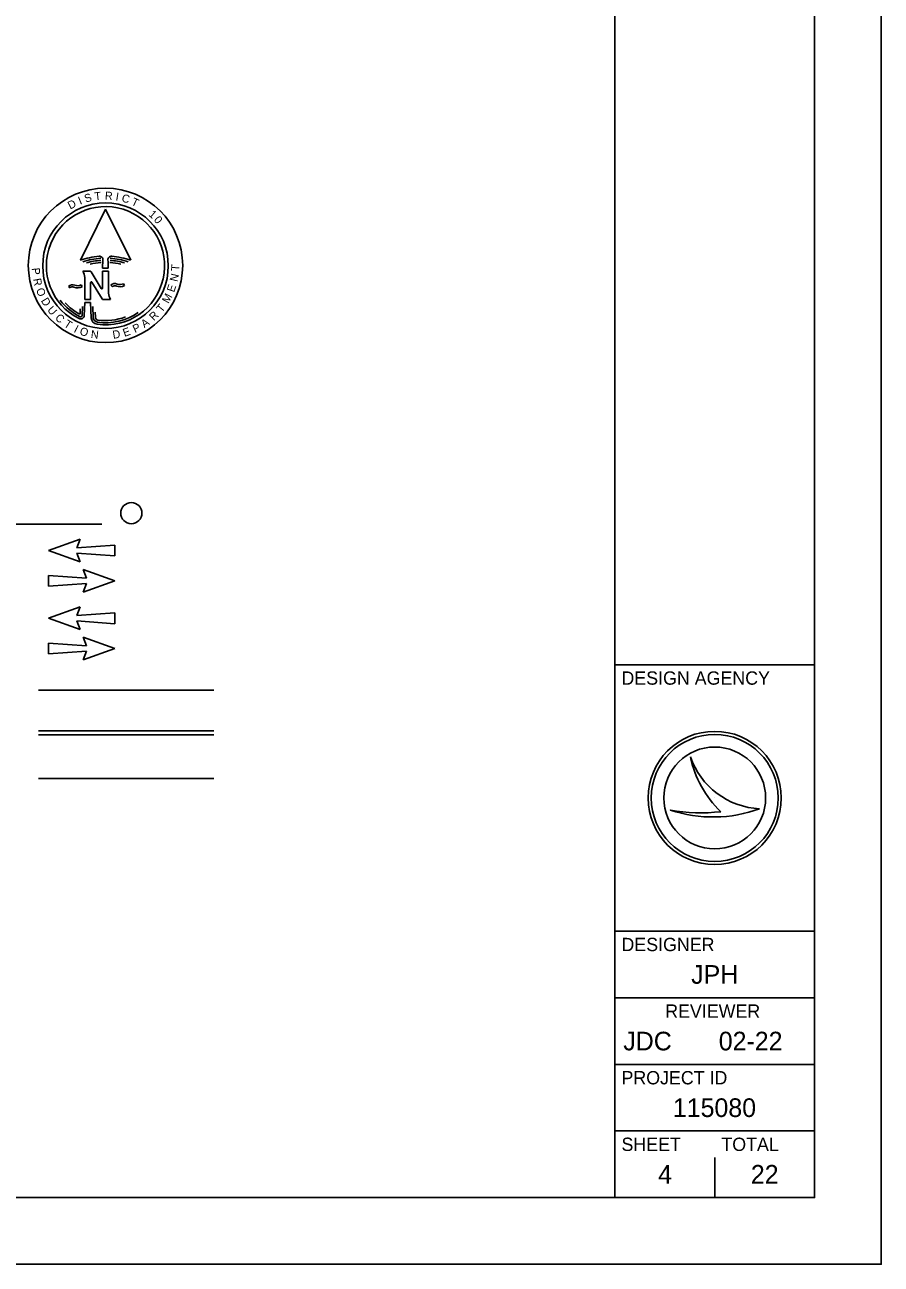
# Model space of a CAD drawing. Extents: x 0 to 34, y 0 to 22.
# Drawn here: x 27.57 to 34, y 0 to 9.3 of the extents above; entities that cross this region are included whole.
import ezdxf

# ---------------------------------------------------------------- set-up
doc = ezdxf.new("R2010")
doc.units = 0
for name, color, linetype in [('Default', 7, 'Continuous'), ('SH_Border', 7, 'Continuous'), ('SH_Cut_Line', 7, 'Continuous'), ('SH_Data', 7, 'Continuous'), ('TX_P_1', 7, 'Continuous')]:
    doc.layers.add(name, color=color, linetype=linetype)

msp = doc.modelspace()

# ---------------------------------------------------------------- linework, layer by layer
at = {"layer": 'Default'}
for p, q in [((27.9872, 7.5356), (28.1762, 7.9196)), ((28.1762, 7.9196), (28.3652, 7.5356)), ((28.1548, 7.4768), (28.1572, 7.5385)), ((28.0049, 7.4554), (28.0587, 7.4554)), ((28.0679, 7.4504), (28.1441, 7.3246)), ((28.1541, 7.3273), (28.1541, 7.4554)), ((28.1541, 7.4554), (28.1978, 7.4554)), ((28.1969, 7.4768), (28.1548, 7.4768)), ((28.1761, 7.4949), (28.1761, 7.4949)), ((28.1761, 7.4949), (28.1761, 7.4949)), ((28.1762, 7.4949), (28.1762, 7.4949)), ((28.1762, 7.4949), (28.1762, 7.4949)), ((28.1762, 7.4949), (28.1762, 7.4949)), ((28.1762, 7.4949), (28.1762, 7.4949)), ((28.1978, 7.4554), (28.1978, 7.2896)), ((28.0012, 7.3379), (27.9935, 7.3518)), ((28.0209, 7.2414), (28.0209, 7.4072)), ((28.0647, 7.3695), (28.0647, 7.2414)), ((28.1509, 7.2466), (28.0747, 7.3723)), ((28.3196, 7.3465), (28.3119, 7.3603)), ((27.8982, 7.3394), (27.9098, 7.3284)), ((28.2166, 7.3481), (28.2283, 7.3371)), ((27.9867, 7.1716), (27.9847, 7.1303)), ((28.0034, 7.1895), (28.0003, 7.1214)), ((28.0209, 7.22), (28.0162, 7.1202)), ((28.0647, 7.2414), (28.0209, 7.2414)), ((28.0647, 7.22), (28.0209, 7.22)), ((28.068, 7.1049), (28.0647, 7.22)), ((28.0817, 7.1887), (28.084, 7.1073)), ((28.2139, 7.2414), (28.16, 7.2414)), ((28.099, 7.1453), (28.1, 7.1078)), ((28.1475, 5.5549), (23.1299, 5.5549)), ((27.748, 5.3577), (27.9859, 5.4429)), ((27.9859, 5.4429), (27.9606, 5.3781)), ((27.9606, 5.3781), (28.2465, 5.3983)), ((28.2465, 5.3983), (28.2465, 5.3167)), ((27.9859, 5.2722), (27.748, 5.3577)), ((28.2465, 5.3167), (27.9607, 5.3371)), ((27.9607, 5.3371), (27.9859, 5.2722)), ((28.0339, 5.1506), (28.0085, 5.2154)), ((28.0085, 5.2154), (28.2467, 5.13)), ((27.7481, 5.0894), (27.7479, 5.1706)), ((27.7479, 5.1706), (28.0339, 5.1506)), ((28.2467, 5.13), (28.0088, 5.0448)), ((28.0339, 5.1094), (27.7481, 5.0894)), ((28.0088, 5.0448), (28.0339, 5.1094)), ((27.748, 4.849), (27.9859, 4.9342)), ((27.9859, 4.9342), (27.9606, 4.8694)), ((27.9859, 4.7635), (27.748, 4.849)), ((27.9606, 4.8694), (28.2465, 4.8896)), ((28.2465, 4.8896), (28.2465, 4.808)), ((28.2465, 4.808), (27.9607, 4.8285)), ((27.9607, 4.8285), (27.9859, 4.7635)), ((27.7481, 4.5807), (27.7479, 4.6619)), ((27.7479, 4.6619), (28.0339, 4.6419)), ((28.0339, 4.6419), (28.0085, 4.7067)), ((28.0085, 4.7067), (28.2467, 4.6213)), ((28.0339, 4.6008), (27.7481, 4.5807)), ((28.2467, 4.6213), (28.0088, 4.5361)), ((28.0088, 4.5361), (28.0339, 4.6008)), ((28.9905, 4.3084), (27.6732, 4.3084)), ((28.9905, 4.0047), (27.6732, 4.0047)), ((28.9905, 3.9748), (27.6732, 3.9748)), ((28.9905, 3.6461), (27.6732, 3.6461))]:
    msp.add_line(p, q, dxfattribs=at)
for centre, radius in [((28.1761, 7.4975), 0.5795), ((28.1761, 7.4948), 0.4715)]:
    msp.add_circle(centre, radius, dxfattribs=at)
for centre, radius, start, end in [((28.1761, 7.4948), 0.4438, 261.93684, 243.42086), ((28.1761, 7.0035), 0.5647, 94.8642, 109.5471), ((28.1761, 7.0035), 0.5486, 93.73826, 108.099), ((28.1305, 7.5395), 0.0267, 357.77965, 94.8642), ((28.2212, 7.5395), 0.0267, 85.19546, 182.12377), ((40.4649, 7.9936), 12.2788, 182.12377, 182.41208), ((28.1761, 7.0035), 0.5486, 71.901, 86.26141), ((28.1761, 7.0035), 0.5647, 70.45266, 85.19546), ((27.8939, 7.3917), 0.128, 7.00127, 29.86863), ((28.1761, 7.0035), 0.5326, 93.73826, 105.49674), ((28.0587, 7.4447), 0.0107, 31.24731, 90), ((28.1761, 7.0035), 0.5165, 93.73826, 102.75761), ((28.1761, 7.0035), 0.5165, 77.24239, 86.26141), ((28.1761, 7.0035), 0.5326, 74.50326, 86.26141), ((27.9288, 7.3106), 0.0421, 65.79325, 136.76575), ((27.9669, 7.3987), 0.0539, 247.19582, 299.48448), ((28.0701, 7.3695), 0.00535, 31.24622, 180), ((28.2472, 7.3193), 0.0421, 65.79325, 136.76575), ((28.2854, 7.4073), 0.0539, 247.19582, 299.48448), ((27.9288, 7.3106), 0.026, 65.79325, 136.76575), ((27.9667, 7.3988), 0.07, 247.19582, 299.48448), ((28.1487, 7.3274), 0.00535, 211.24622, 0), ((28.3249, 7.3052), 0.128, 187.00127, 209.86863), ((28.2472, 7.3193), 0.026, 65.79325, 136.76575), ((28.2852, 7.4074), 0.07, 247.19582, 299.48448), ((28.1761, 7.4948), 0.4277, 217.27521, 243.42077), ((28.1761, 7.4948), 0.4117, 222.56637, 242.2942), ((28.16, 7.2521), 0.0107, 211.24731, 270), ((27.9896, 7.1219), 0.0267, 243.42086, 356.26509), ((27.9896, 7.1219), 0.0107, 243.42077, 357.31292), ((28.1214, 7.1084), 0.0535, 183.80636, 261.93684), ((28.1214, 7.1084), 0.0374, 181.63859, 261.94105), ((28.1214, 7.1084), 0.0214, 181.63732, 261.93938), ((28.1761, 7.4948), 0.4277, 261.94105, 304.81679), ((28.1761, 7.4948), 0.4117, 261.93938, 291.31687)]:
    msp.add_arc(centre, radius, start, end, dxfattribs=at)
at = {"layer": 'SH_Border'}
for p, q in [((32, 0.5), (32, 21.5)), ((32, 4.5), (33.5, 4.5)), ((32, 2.5), (33.5, 2.5)), ((32, 2), (33.5, 2)), ((32, 1.5), (33.5, 1.5)), ((32, 1), (33.5, 1))]:
    msp.add_line(p, q, dxfattribs=at)
msp.add_lwpolyline([(1.5, 21.5), (33.5, 21.5), (33.5, 0.5), (1.5, 0.5)], close=True, dxfattribs=at)
at = {"layer": 'SH_Cut_Line'}
msp.add_lwpolyline([(0, 0), (34, 0), (34, 22), (0, 22)], close=True, dxfattribs=at)
at = {"layer": 'SH_Data'}
for p, q in [((32.5674, 3.8096), (32.5675, 3.8096)), ((32.75, 3.5), (32.75, 3.5)), ((32.4172, 3.4095), (32.4172, 3.4095)), ((33.0873, 3.4185), (33.0873, 3.4185)), ((32.75, 0.5), (32.75, 0.8)), ((32.375, 0.675), (32.375, 0.675))]:
    msp.add_line(p, q, dxfattribs=at)
for radius in [0.5, 0.4768, 0.4768, 0.3822]:
    msp.add_circle((32.75, 3.5), radius, dxfattribs=at)
for centre, radius, start, end in [((33.1159, 3.9976), 0.5798, 198.92567, 198.93195), ((33.3467, 3.9701), 0.7956, 191.63793, 191.64215), ((33.1159, 3.9976), 0.5798, 198.93195, 267.16574), ((33.3467, 3.9701), 0.7956, 191.64215, 226.09467), ((32.7394, 4.37), 1.0131, 251.45764, 290.08324), ((32.648, 4.6543), 1.2661, 259.49639, 259.49952), ((32.7394, 4.37), 1.0131, 251.45274, 251.45764), ((32.648, 4.6543), 1.2661, 259.49952, 276.66723)]:
    msp.add_arc(centre, radius, start, end, dxfattribs=at)
at = {"layer": 'TX_P_1'}
msp.add_circle((28.3702, 5.6378), 0.0797, dxfattribs=at)

# ---------------------------------------------------------------- texts
at = {"layer": 'Default'}
for s, rotation, p in [('I', 22.18433, (27.9853, 7.9527)), ('S', 16.96646, (28.0273, 7.9681)), ('T', 6.5307, (28.0967, 7.9852)), ('R', 356.09495, (28.1699, 7.9926)), ('I', 350.87707, (28.2493, 7.9856)), ('C', 345.6592, (28.2932, 7.977)), ('T', 335.22345, (28.3644, 7.9542)), ('D', 27.40221, (27.9113, 7.9161)), ('1', 319.56982, (28.4955, 7.8737)), ('0', 309.13407, (28.5352, 7.8382)), ('P', 275.23459, (27.6221, 7.477)), ('T', 87.40778, (28.7285, 7.4547)), ('R', 280.45247, (27.6321, 7.3954)), ('E', 71.77087, (28.6912, 7.2918)), ('N', 76.98874, (28.7152, 7.3716)), ('O', 290.88822, (27.6531, 7.3153)), ('D', 301.32397, (27.6891, 7.2328)), ('M', 61.33512, (28.6485, 7.2073)), ('U', 311.75972, (27.735, 7.1603)), ('T', 50.89936, (28.5985, 7.1394)), ('C', 316.9776, (27.7929, 7.0979)), ('T', 327.41335, (27.859, 7.0431)), ('A', 35.24574, (28.4682, 7.0259)), ('R', 45.68149, (28.5398, 7.0776)), ('I', 332.63123, (27.9337, 6.9996)), ('O', 343.06698, (27.9773, 6.9793)), ('N', 353.50273, (28.0636, 6.9531)), ('D', 9.15636, (28.2341, 6.9461)), ('E', 19.59211, (28.3188, 6.9605)), ('P', 24.80999, (28.3968, 6.9897))]:
    msp.add_text(s, height=0.0601, rotation=rotation, dxfattribs=at).set_placement(p)
at = {"layer": 'SH_Data'}
for s, height, p in [('DESIGN AGENCY', 0.1, (32.05, 4.35)), ('DESIGNER', 0.1, (32.05, 2.35)), ('JPH', 0.14, (32.5731, 2.105)), ('REVIEWER', 0.1, (32.3783, 1.85)), ('JDC', 0.14, (32.0637, 1.605)), ('02-22', 0.14, (32.7802, 1.605)), ('PROJECT ID', 0.1, (32.05, 1.35)), ('115080', 0.14, (32.4357, 1.105)), ('SHEET', 0.1, (32.05, 0.85)), ('TOTAL', 0.1, (32.8, 0.85)), ('4', 0.14, (32.3254, 0.605)), ('22', 0.14, (33.0214, 0.605))]:
    msp.add_text(s, height=height, dxfattribs=at).set_placement(p)

doc.saveas('drawing.dxf')
